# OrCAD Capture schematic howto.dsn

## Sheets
1 02_MICRO: size B; title: HOWTO_VIDEOS; rev: A; note: 1.0
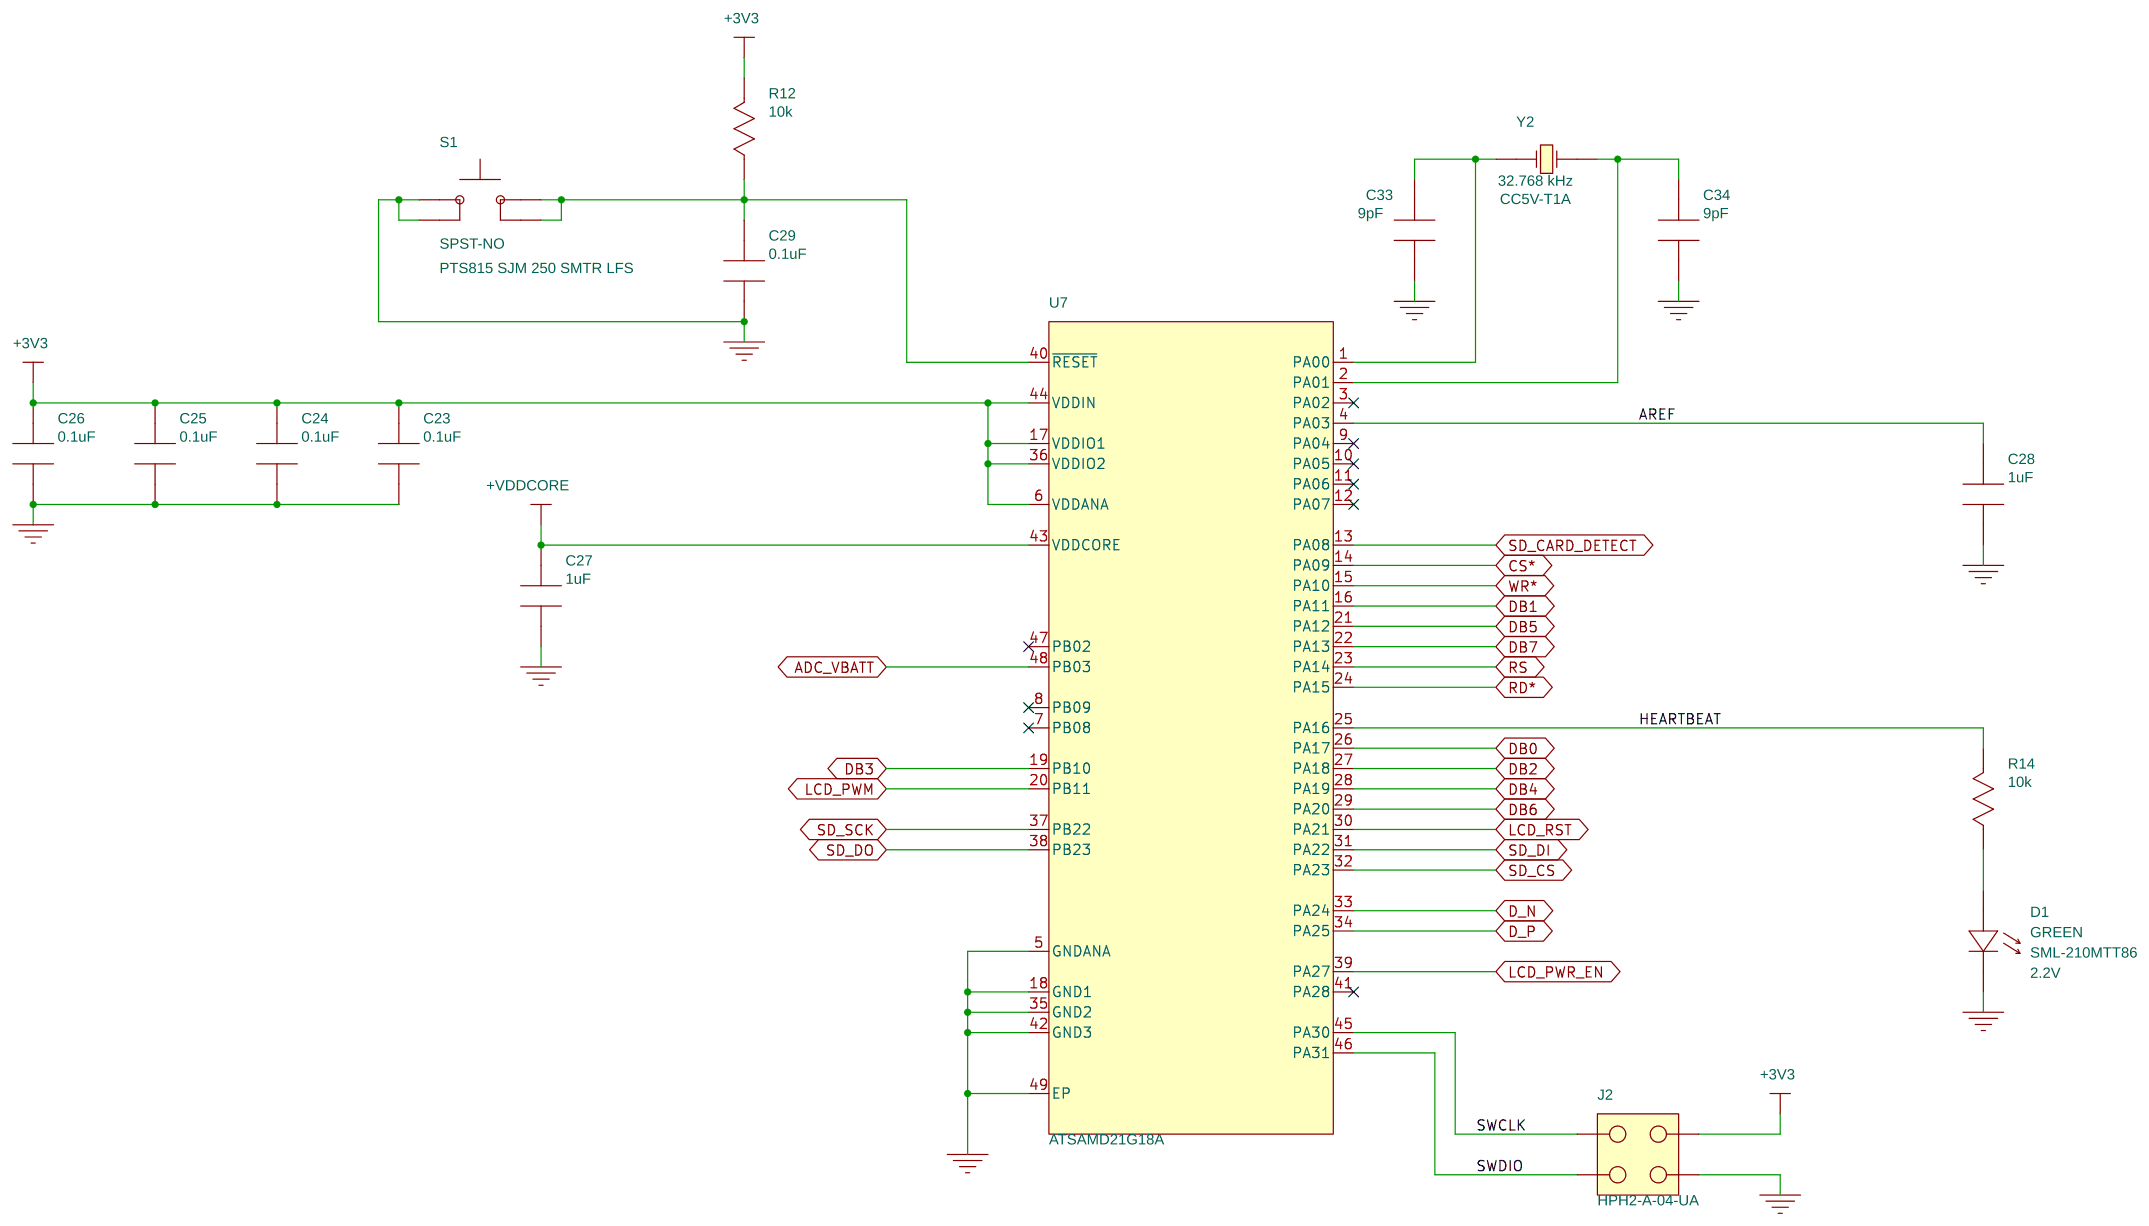
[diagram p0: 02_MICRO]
2 01_POWER: size B
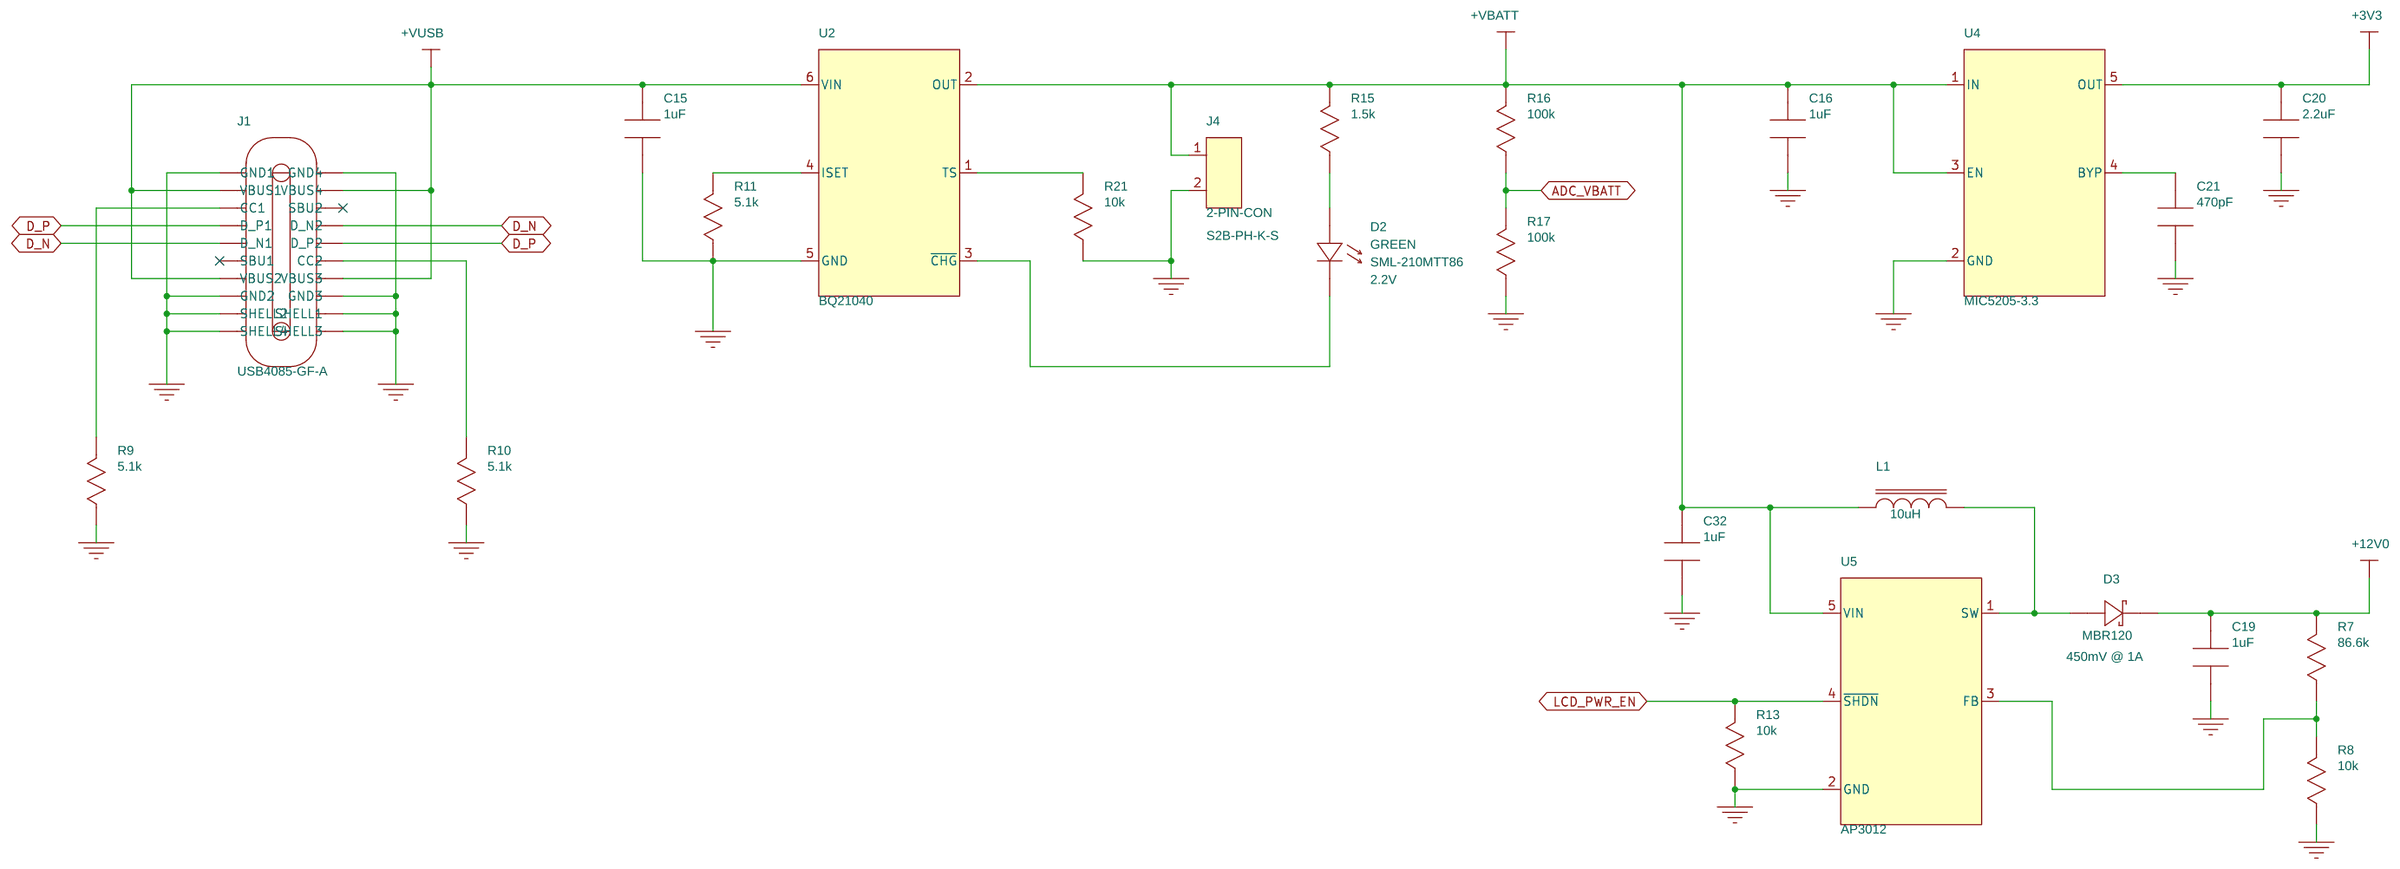
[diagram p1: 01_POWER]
3 03_PERIPHERALS: size B
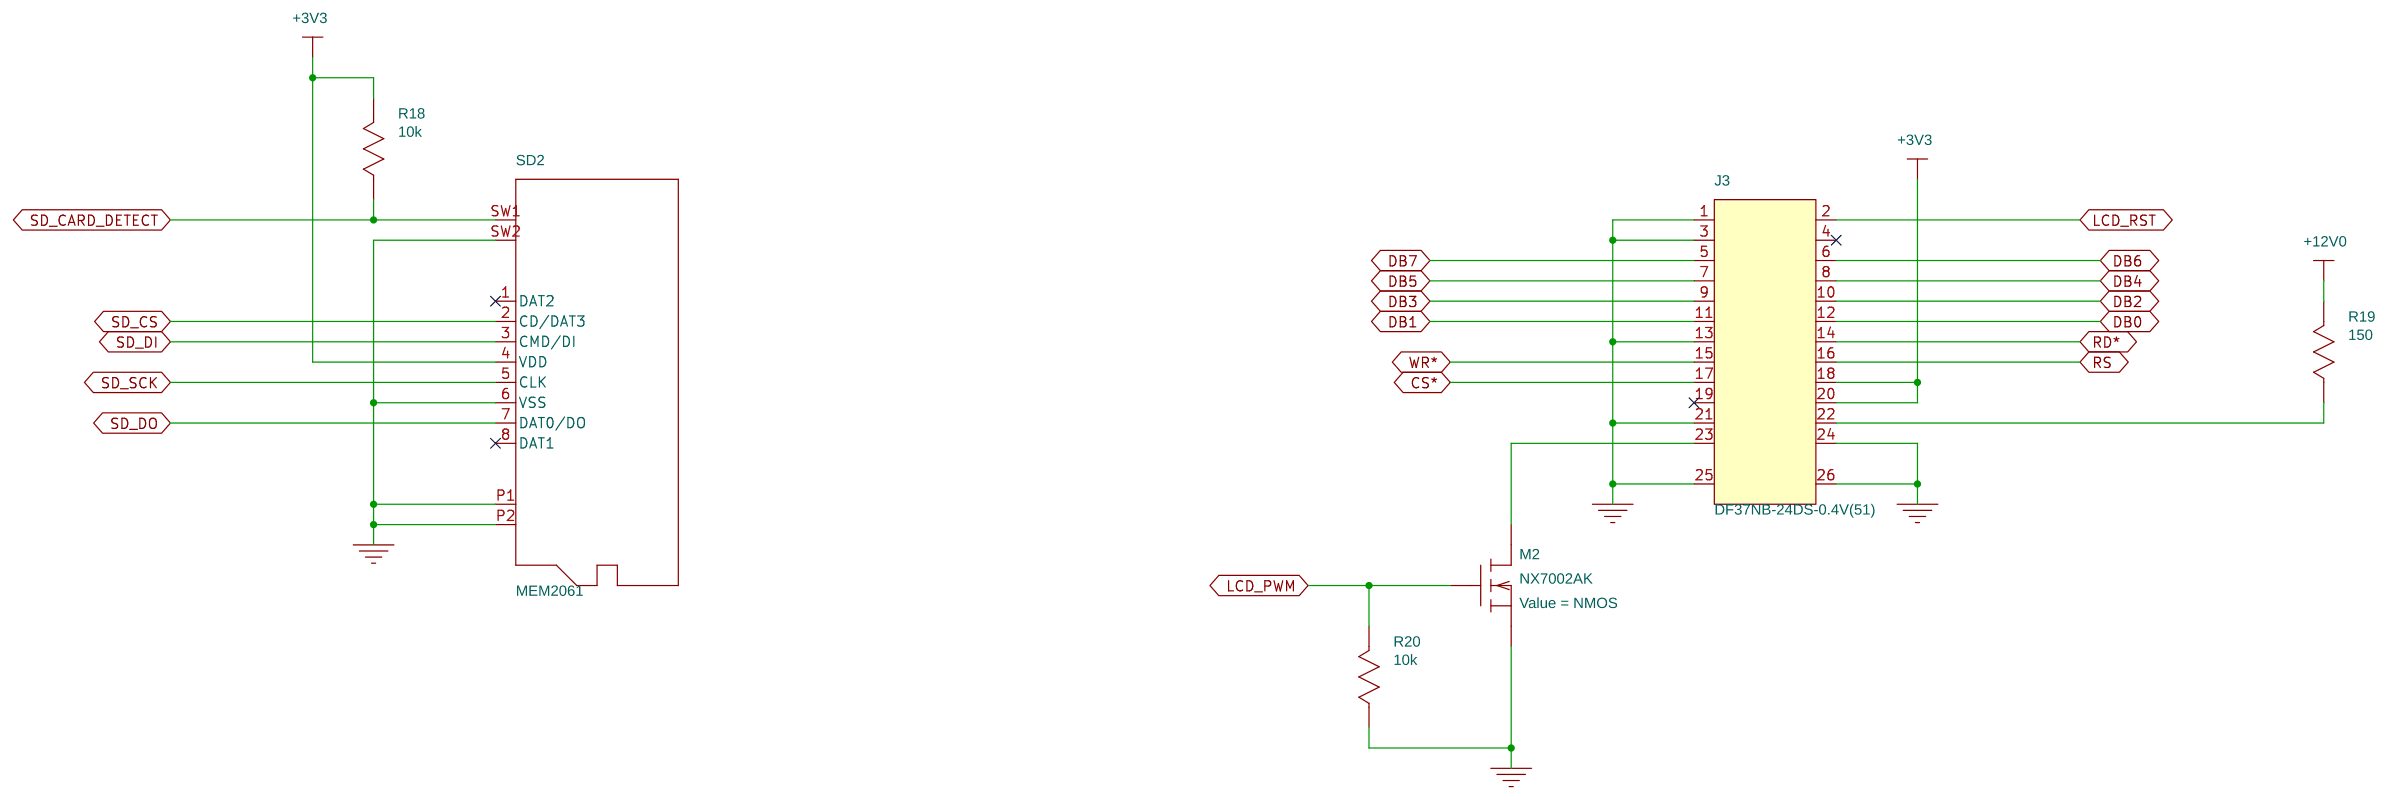
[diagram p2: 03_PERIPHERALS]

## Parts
sheet 01_POWER
C15  1uF  [cap0603]
C16  1uF  [cap0603]
C19  1uF  [cap0603]
C20  2.2uF  [cap0603]
C21  470pF  [cap0603]
C32  1uF  [cap0603]
D2  GREEN  [res0805]
D3  SCHOTTKY_DIODE  [SOD-123FL]
J1  USB4085-GF-A  [usb4085-gf-a]
J4  2-PIN-CON  [s2b-ph-k]
L1  10uH  [ind0805]
R7  86.6k  [res0603]
R8  10k  [res0603]
R9  5.1k  [res0603]
R10  5.1k  [res0603]
R11  5.1k  [res0603]
R13  10k  [res0603]
R15  1.5k  [res0603]
R16  100k  [res0603]
R17  100k  [res0603]
R21  10k  [res0603]
U2  BQ21040  [sot-23-6]
U4  MIC5205-3.3YM5-TR  [sot-23-5]
U5  AP3012_IC  [sot-23-5]
sheet 02_MICRO
C23  0.1uF  [cap0603]
C24  0.1uF  [cap0603]
C25  0.1uF  [cap0603]
C26  0.1uF  [cap0603]
C27  1uF  [cap0603]
C28  1uF  [cap0603]
C29  0.1uF  [cap0603]
C33  9pF  [cap0603]
C34  9pF  [cap0603]
D1  GREEN  [res0805]
J2  HEADER VERT 2X2  [2x2-header-50mil-vert]
R12  10k  [res0603]
R14  10k  [res0603]
S1  SPST-NO  [PTS815-SJM-250-SMTR-LFS]
U7  ATSAMD21G18A-MF  [48qfn_7x7]
Y2  32.768 kHz  [2-smd]
sheet 03_PERIPHERALS
J3  DF37NB-24DS-0.4V  [DF37NB-24DS-0]
M2  NMOS  [sot-23-3]
R18  10k  [res0603]
R19  150  [res0805]
R20  10k  [res0603]
SD2  MEM2061  [MEM2061]

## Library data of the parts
C15 C16 C19 C32 = CAP1: Manufacturer Name: SAMSUNG; Manufacturer Part Number: CL10A105KA8NNNC; PACKAGE: 0603; Part Number: CDN-CAP-0002; ROOM: POWER; TC: X5R; VOLTAGE: 25V; cdn_wsid: local
C20 = CAP1: Manufacturer Name: SAMSUNG; Manufacturer Part Number: CL10A225KO8NNNC; PACKAGE: 0603; Part Number: CDN-CAP-0003; ROOM: POWER; TC: X5R; VOLTAGE: 16V; cdn_wsid: local
C21 = CAP1: Manufacturer Name: KEMET; Manufacturer Part Number: C0603C471J5GAC7867; PACKAGE: 0603; Part Number: CDN-CAP-0005; ROOM: POWER; TC: C0G/NP0; VOLTAGE: 50V; cdn_wsid: local
D2 = SML-210MTT86: CURRENT: 25mA; IR: 100uA; Manufacturer Name: ROHM Semiconductor; PACKAGE: 0805; POWER: 70mW; Part Number: CDN-DIO-0002; ROOM: POWER; VF: 2.2V; VR: 4V; cdn_wsid: local
D3 = SCHOTTKY_DIODE: CURRENT: 1A; GENERIC_NAME: MBR120; IR: 400uA @ 20V; Manufacturer Name: onsemi; Manufacturer Part Number: MBR120LSFT1G; POWER: 450mW; Part Number: CDN-DIO-0001; ROOM: POWER; VF: 450mV @ 1A; VR: 20V; cdn_wsid: local
J1 = USB4085-GF-A: CURRENT: 5A; MOUNTING_TYPE: Through Hole, Right Angle; Manufacturer Name: GCT (GLOBAL CONNECTOR TECHNOLOGY); Part Number: CDN-CON-0001; ROOM: POWER; VOLTAGE: 48VDC; cdn_wsid: local
J4 = 2-PIN-CON: CURRENT: 2A; GENERIC_NAME: S2B-PH-K-S; MOUNTING_TYPE: Through Hole, Right Angle; Manufacturer Name: JST (JAPAN SOLDERLESS TERMINALS); Manufacturer Part Number: S2B-PH-K-S; Part Number: CDN-CON-0002; ROOM: POWER; VOLTAGE: 100V AC/DC; cdn_wsid: local
L1 = IND: CURRENT: 520mA; DCR: 650mR; Manufacturer Name: TAIYO YUDEN; Manufacturer Part Number: CB2012T100MR; PACKAGE: 0805; Part Number: CDN-IND-0001; ROOM: POWER; SRF: 32MHz; TOL: 20%; cdn_wsid: local
R7 = RES1: Manufacturer Name: Stackpole Electronics, Inc.; Manufacturer Part Number: RMCF0603FT86K6; PACKAGE: 0603; POWER: 0.1W; Part Number: CDN-RES-0005; ROOM: POWER; TOL: 1%; cdn_wsid: local
R8 R13 R21 = RES1: Manufacturer Name: Stackpole Electronics, Inc.; Manufacturer Part Number: RMCF0603FT10K0; PACKAGE: 0603; POWER: 0.1W; Part Number: CDN-RES-0004; ROOM: POWER; TOL: 1%; cdn_wsid: local
R9-R11 = RES1: Manufacturer Name: YAGEO; Manufacturer Part Number: RC0603FR-135K1L; PACKAGE: 0603; POWER: 0.1W; Part Number: CDN-RES-0003; ROOM: POWER; TOL: 1%; cdn_wsid: local
R15 = RES1: Manufacturer Name: Walsin Technology Corporation; Manufacturer Part Number: WR06X1501FTL; PACKAGE: 0603; POWER: 0.1W; Part Number: CDN-RES-0001; ROOM: POWER; TOL: 1%; cdn_wsid: local
R16 R17 = RES1: Manufacturer Name: Stackpole Electronics, Inc.; Manufacturer Part Number: RMCF0603FT100K; PACKAGE: 0603; POWER: 0.1W; Part Number: CDN-RES-0002; ROOM: POWER; TOL: 1%; cdn_wsid: local
U2 = BQ21040: Manufacturer Name: Texas Instruments; Manufacturer Part Number: BQ21040DBVT; Part Number: CDN-IC-0001; ROOM: POWER; VOLTAGE_SUPPLY: 4.45V-6.45V; cdn_wsid: local
U4 = MIC5205-3.3YM5-TR: GENERIC_NAME: MIC5205-3.3; Manufacturer Name: Microchip; Part Number: CDN-IC-0002; ROOM: POWER; VOLTAGE_SUPPLY: 3.65V-16V; cdn_wsid: local
U5 = AP3012_IC: GENERIC_NAME: AP3012; Manufacturer Name: Diodes Incorporated; Manufacturer Part Number: AP3012KTR-E1; Part Number: CDN-IC-0003; ROOM: POWER; VOLTAGE_SUPPLY: 2.6V-16V; cdn_wsid: local
C23-C26 = CAP1: Manufacturer Name: SAMSUNG; Manufacturer Part Number: CL10B104KB8NNWC; PACKAGE: 0603; Part Number: CDN-CAP-0001; ROOM: UC; TC: X7R; VOLTAGE: 50V; cdn_wsid: local
C27 C28 = CAP1: Manufacturer Name: SAMSUNG; Manufacturer Part Number: CL10A105KA8NNNC; PACKAGE: 0603; Part Number: CDN-CAP-0002; ROOM: UC; TC: X5R; VOLTAGE: 25V; cdn_wsid: local
C29 = CAP1: Manufacturer Name: SAMSUNG; Manufacturer Part Number: CL10B104KB8NNWC; PACKAGE: 0603; Part Number: CDN-CAP-0001; TC: X7R; VOLTAGE: 50V; cdn_wsid: local
C33 C34 = CAP1: Manufacturer Name: Murata Electronics; Manufacturer Part Number: GRM1885C1H9R0DA01D; PACKAGE: 0603; Part Number: CDN-CAP-0006; ROOM: UC; TC: C0G/NP0; VOLTAGE: 50V; cdn_wsid: local
D1 = SML-210MTT86: CURRENT: 25mA; IR: 100uA; Manufacturer Name: ROHM Semiconductor; PACKAGE: 0805; POWER: 70mW; Part Number: CDN-DIO-0002; ROOM: UC; VF: 2.2V; VR: 4V; cdn_wsid: local
J2 = HEADER_VERT_2X2: CURRENT: 1A; GENERIC_NAME: HPH2-A-04-UA; MOUNTING_TYPE: Through Hole; Manufacturer Name: Adam Tech; Manufacturer Part Number: HPH2-A-04-UA; Part Number: CDN-CON-0003; VOLTAGE: 250VAC; cdn_wsid: local
R12 = RES1: Manufacturer Name: Stackpole Electronics, Inc.; Manufacturer Part Number: RMCF0603FT10K0; PACKAGE: 0603; POWER: 0.1W; Part Number: CDN-RES-0004; TOL: 1%; cdn_wsid: local
R14 = RES1: Manufacturer Name: Stackpole Electronics, Inc.; Manufacturer Part Number: RMCF0603FT10K0; PACKAGE: 0603; POWER: 0.1W; Part Number: CDN-RES-0004; ROOM: UC; TOL: 1%; cdn_wsid: local
S1 = PTS815_SJM_250_SMTR_LFS: CURRENT: 50mA; GENERIC_NAME: PTS815 SJM 250 SMTR LFS; MOUNTING_TYPE: SMD; Manufacturer Name: C & K COMPONENTS; Manufacturer Part Number: PTS815 SJM 250 SMTR LFS; Part Number: CDN-SWT-0001; VOLTAGE: 12V; cdn_wsid: local
U7 = ATSAMD21G18A-MF: GENERIC_NAME: ATSAMD21G18A; Manufacturer Name: Microchip; Part Number: CDN-IC-0004; ROOM: UC; VOLTAGE_SUPPLY: 1.62V-3.6V; cdn_wsid: local
Y2 = CC5V-T1A-32.768KHZ-9PF: DCR: 70k; GENERIC_NAME: CC5V-T1A; LOAD_CAPACITANCE: 9pF; Manufacturer Name: Micro Crystal AG; Manufacturer Part Number: CC5V-T1A-32.768KHZ-9PF-20PPM-TA-QC; Part Number: CDN-XTL-0001; ROOM: UC; TOL: 20%; cdn_wsid: local
J3 = DF37NB-24DS-0.4V: CURRENT: 0.3A; GENERIC_NAME: DF37NB-24DS-0.4V(51); MOUNTING_TYPE: Surface Mount; Manufacturer Name: Hirose; Manufacturer Part Number: DF37NB-24DS-0.4V(51); Part Number: CDN-CON-0005; ROOM: LCD; VOLTAGE: 30VAC; cdn_wsid: local
M2 = NMOS: GENERIC_NAME: NX7002AK; Manufacturer Name: Nexperia; Manufacturer Part Number: NX7002AKVL; POWER: 265mW; Part Number: CDN-TRT-0001; ROOM: LCD; TECHNOLOGY: MOSFET N-Channel; cdn_wsid: local
R18 = RES1: Manufacturer Name: Stackpole Electronics, Inc.; Manufacturer Part Number: RMCF0603FT10K0; PACKAGE: 0603; POWER: 0.1W; Part Number: CDN-RES-0004; ROOM: SD; TOL: 1%; cdn_wsid: local
R19 = RES1: Manufacturer Name: KOA Speer; Manufacturer Part Number: SG73P2ATTD1500F; PACKAGE: 0805; POWER: 0.5W; Part Number: CDN-RES-0006; ROOM: LCD; TOL: 1%; cdn_wsid: local
R20 = RES1: Manufacturer Name: Stackpole Electronics, Inc.; Manufacturer Part Number: RMCF0603FT10K0; PACKAGE: 0603; POWER: 0.1W; Part Number: CDN-RES-0004; ROOM: LCD; TOL: 1%; cdn_wsid: local
SD2 = MEM2061: CURRENT: 0.5A; MOUNTING_TYPE: Surface Mount; Manufacturer Name: GLOBAL CONNECTOR TECHNOLOGY; Manufacturer Part Number: MEM2061-01-188-00-A; Part Number: CDN-CON-0004; ROOM: SD; VOLTAGE: 100VAC; cdn_wsid: local

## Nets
+3V3: C20.1 C23.1 C24.1 C25.1 C26.1 J2.3 J3.18 J3.20 R12.1 R18.1 SD2.4(VDD) U4.5(OUT) U7.6(VDDANA) U7.17(VDDIO1) U7.36(VDDIO2) U7.44(VDDIN)
+12V0: C19.1 D3.2 R7.1 R19.1
+VBATT: C16.1 C32.1 J4.1 L1.1 R15.1 R16.1 U2.2(OUT) U4.1(IN) U4.3(EN) U5.5(VIN)
+VDDCORE: C27.1 U7.43(VDDCORE)
GND: C15.2 C16.2 C19.2 C20.2 C21.2 C23.2 C24.2 C25.2 C26.2 C27.2 C28.2 C29.2 C32.2 C33.2 C34.2 D1.2(K) J1.A1(GND1) J1.A12(GND2) J1.B1(GND3) J1.B12(GND4) J1.MNT1(SHELL1) J1.MNT2(SHELL2) J1.MNT3(SHELL3) J1.MNT4(SHELL4) J2.4 J3.1 J3.3 J3.13 J3.21 J3.24 J3.25 J3.26 J4.2 M2.1(s) R8.2 R9.2 R10.2 R11.2 R13.2 R17.2 R20.2 R21.2 S1.1 S1.3 SD2.6(VSS) SD2.P1 SD2.P2 SD2.SW2 U2.5(GND) U4.2(GND) U5.2(GND) U7.5(GNDANA) U7.18(GND1) U7.35(GND2) U7.42(GND3) U7.49(EP)
+VUSB: C15.1 J1.A4(VBUS1) J1.A9(VBUS2) J1.B4(VBUS3) J1.B9(VBUS4) U2.6(VIN)
ADC_VBATT: R16.2 R17.1 U7.48(PB03)
AREF: C28.1 U7.4(PA03)
CS*: J3.17 U7.14(PA09)
D_N: J1.A7(D_N1) J1.B7(D_N2) U7.33(PA24)
D_P: J1.A6(D_P1) J1.B6(D_P2) U7.34(PA25)
DB0: J3.12 U7.26(PA17)
DB1: J3.11 U7.16(PA11)
DB2: J3.10 U7.27(PA18)
DB3: J3.9 U7.19(PB10)
DB4: J3.8 U7.28(PA19)
DB5: J3.7 U7.21(PA12)
DB6: J3.6 U7.29(PA20)
DB7: J3.5 U7.22(PA13)
HEARTBEAT: R14.1 U7.25(PA16)
LCD_PWM: M2.3(g) R20.1 U7.20(PB11)
LCD_PWR_EN: R13.1 U5.4(~{SHDN}) U7.39(PA27)
LCD_RST: J3.2 U7.30(PA21)
RD*: J3.14 U7.24(PA15)
RS: J3.16 U7.23(PA14)
SD_CARD_DETECT: R18.2 SD2.SW1 U7.13(PA08)
SD_CS: SD2.2(CD/DAT3) U7.32(PA23)
SD_DI: SD2.3(CMD/DI) U7.31(PA22)
SD_DO: SD2.7(DAT0/DO) U7.38(PB23)
SD_SCK: SD2.5(CLK) U7.37(PB22)
SWCLK: J2.1 U7.45(PA30)
SWDIO: J2.2 U7.46(PA31)
WR*: J3.15 U7.15(PA10)
N16101: R11.1 U2.4(ISET)
N16105: R21.1 U2.1(TS)
N16109: D2.1(A) R15.2
N16135: C21.1 U4.4(BYP)
N16265: J1.A5(CC1) R9.1
N16367: J1.B5(CC2) R10.1
N16387: D2.2(K) U2.3(~{CHG})
N16591: D3.1 L1.2 U5.1(SW)
N16791: R7.2 R8.1 U5.3(FB)
N18102: C33.1 U7.1(PA00) Y2.1
N18118: C34.1 U7.2(PA01) Y2.2
N18134: C29.1 R12.2 S1.2 S1.4 U7.40(~{RESET})
N18980: D1.1(A) R14.2
N20436: J3.22 R19.2
N20456: J3.23 M2.2(d)

Not connected (* = marked no-connect by the designer): J1 A8(SBU1)* B8(SBU2)*; J3 4* 19*; SD2 1(DAT2)* 8(DAT1)*; U7 3(PA02)* 7(PB08)* 8(PB09)* 9(PA04)* 10(PA05)* 11(PA06)* 12(PA07)* 41(PA28)* 47(PB02)*
